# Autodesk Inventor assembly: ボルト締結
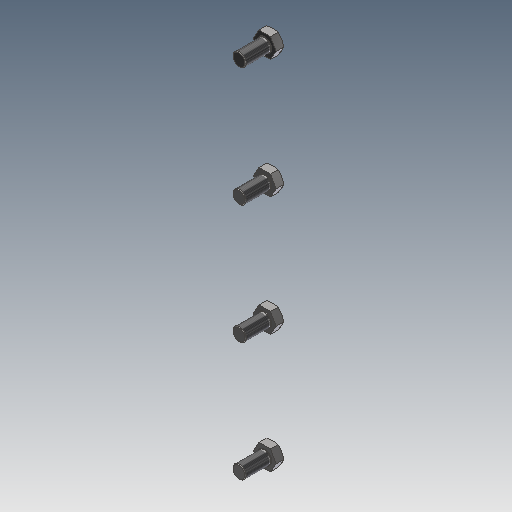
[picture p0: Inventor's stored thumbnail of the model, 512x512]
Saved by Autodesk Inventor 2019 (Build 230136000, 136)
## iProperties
Created: 2018-04
Part Number: ボルト締結
Document SubType Name: Assembly
Designer: shimont
Mass: 3164.95 g
Surface Area: 578.014 cm^2
Volume: 403.178 cm^3
Density: 7.85 g/cm^3
ClientObjectVersion: 1
Author: shimont
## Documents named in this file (2)
- C:\Demo\Inventor_Gate\GateAssy\デザイン アクセラレータ\ボルト締結2.iam
- C:\Users\shimont\Documents\Inventor\Content Center Files\R2019\ja-JP\JIS B 1180(2)\JIS B 1180 - M33x65(2).ipt
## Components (4 placed, 1 different names)
1. JIS B 1180 M33x65:1
2. JIS B 1180 M33x65:2
3. JIS B 1180 M33x65:3
4. JIS B 1180 M33x65:4
